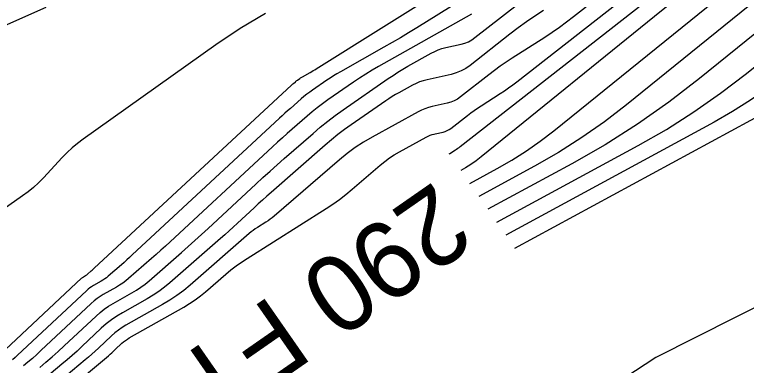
# Model space of a CAD drawing. Extents: x 1768942 to 1774819, y 723037 to 732099.
# Drawn here: x 1770698.5 to 1770755.9, y 726606.2 to 726633.7 of the extents above; entities that cross this region are included whole.
import ezdxf

# ---------------------------------------------------------------- set-up
doc = ezdxf.new("R2010")
doc.units = 0
doc.layers.add('R_Contour Annot', color=7, linetype='Continuous')
doc.layers.add('R_Contours', color=7, linetype='Continuous')

msp = doc.modelspace()

# ---------------------------------------------------------------- linework, layer by layer
at = {"layer": 'R_Contours'}
for points in [[(1770734.178, 726620.492), (1770736.32, 726621.654), (1770737.482, 726622.319), (1770738.61, 726623.036), (1770739.704, 726623.803), (1770740.764, 726624.622), (1770770.803, 726648.931), (1770771.01, 726649.103), (1770771.211, 726649.281), (1770771.408, 726649.465), (1770771.599, 726649.654), (1770772.459, 726650.529), (1770772.596, 726650.666), (1770772.736, 726650.8), (1770772.879, 726650.931), (1770773.024, 726651.059), (1770773.61, 726651.567), (1770773.758, 726651.692), (1770773.909, 726651.812), (1770774.064, 726651.928), (1770774.222, 726652.04), (1770795.506, 726666.687)], [(1770796.101, 726665.831), (1770779.224, 726654.217), (1770778.742, 726653.876), (1770778.271, 726653.522), (1770777.81, 726653.155), (1770777.359, 726652.775), (1770775.575, 726651.229), (1770775.133, 726650.838), (1770774.699, 726650.439), (1770774.273, 726650.031), (1770773.855, 726649.615), (1770771.236, 726646.95), (1770770.653, 726646.374), (1770770.056, 726645.815), (1770769.442, 726645.274), (1770768.813, 726644.75), (1770746.468, 726626.666), (1770744.745, 726625.336), (1770742.966, 726624.088), (1770741.132, 726622.924), (1770739.243, 726621.842), (1770734.884, 726619.477)], [(1770798.2, 726666.01), (1770784.225, 726656.393), (1770783.421, 726655.823), (1770782.633, 726655.232), (1770781.862, 726654.618), (1770781.108, 726653.983), (1770778.126, 726651.399), (1770777.387, 726650.746), (1770776.662, 726650.078), (1770775.95, 726649.396), (1770775.252, 726648.7), (1770770.873, 726644.246), (1770769.899, 726643.283), (1770768.9, 726642.349), (1770767.874, 726641.444), (1770766.822, 726640.568), (1770752.171, 726628.711), (1770749.785, 726626.869), (1770747.322, 726625.141), (1770744.783, 726623.528), (1770742.167, 726622.031), (1770735.59, 726618.462)], [(1770736.296, 726617.447), (1770747.368, 726623.455), (1770749.588, 726624.726), (1770751.744, 726626.095), (1770753.835, 726627.562), (1770755.86, 726629.126), (1770764.832, 726636.386), (1770766.306, 726637.615), (1770767.744, 726638.883), (1770769.145, 726640.192), (1770770.51, 726641.541), (1770776.648, 726647.786), (1770777.627, 726648.762), (1770778.625, 726649.718), (1770779.641, 726650.654), (1770780.677, 726651.569), (1770784.858, 726655.191), (1770785.915, 726656.081), (1770786.995, 726656.941), (1770788.099, 726657.771), (1770789.227, 726658.57), (1770797.444, 726664.225)], [(1770797.312, 726662.869), (1770793.302, 726660.109), (1770792.31, 726659.406), (1770791.338, 726658.676), (1770790.387, 726657.919), (1770789.457, 726657.136), (1770783.228, 726651.739), (1770781.896, 726650.561), (1770780.587, 726649.357), (1770779.304, 726648.127), (1770778.044, 726646.871), (1770769.029, 726637.701), (1770767.84, 726636.525), (1770766.619, 726635.384), (1770765.365, 726634.278), (1770764.08, 726633.207), (1770758.875, 726628.995), (1770757.553, 726627.974), (1770756.188, 726627.016), (1770754.78, 726626.123), (1770753.33, 726625.292), (1770737.003, 726616.433)], [(1770737.709, 726615.418), (1770759.293, 726627.13), (1770759.972, 726627.519), (1770760.632, 726627.938), (1770761.271, 726628.386), (1770761.891, 726628.865), (1770764.329, 726630.838), (1770764.931, 726631.339), (1770765.518, 726631.857), (1770766.09, 726632.392), (1770766.647, 726632.943), (1770779.44, 726645.957), (1770780.98, 726647.493), (1770782.55, 726648.997), (1770784.15, 726650.469), (1770785.779, 726651.909), (1770794.896, 726659.807), (1770795.275, 726660.127), (1770795.662, 726660.435), (1770796.058, 726660.732), (1770796.462, 726661.019), (1770798.095, 726662.143)], [(1770732.564, 726622.812), (1770732.623, 726622.85), (1770733.047, 726623.121), (1770733.144, 726623.185), (1770733.239, 726623.25), (1770733.332, 726623.318), (1770733.424, 726623.388), (1770765.828, 726648.746)], [(1770731.47, 726624.384), (1770732.083, 726624.521), (1770732.249, 726624.567), (1770732.407, 726624.632), (1770732.556, 726624.713), (1770732.698, 726624.812), (1770733.985, 726625.823), (1770734.248, 726626.024), (1770734.515, 726626.218), (1770734.787, 726626.406), (1770735.064, 726626.587), (1770736.548, 726627.535), (1770736.886, 726627.757), (1770737.218, 726627.986), (1770737.544, 726628.223), (1770737.865, 726628.468), (1770761.892, 726647.27)], [(1770757.956, 726645.794), (1770742.307, 726633.548), (1770741.757, 726633.128), (1770741.197, 726632.722), (1770740.628, 726632.329), (1770740.049, 726631.95), (1770737.505, 726630.325), (1770737.031, 726630.014), (1770736.565, 726629.692), (1770736.107, 726629.358), (1770735.656, 726629.014), (1770733.45, 726627.282), (1770733.207, 726627.112), (1770732.951, 726626.973), (1770732.681, 726626.863), (1770732.396, 726626.783), (1770731.229, 726626.522), (1770730.941, 726626.448), (1770730.661, 726626.353), (1770730.387, 726626.239), (1770730.122, 726626.105), (1770726.517, 726624.125), (1770725.841, 726623.731), (1770725.188, 726623.302), (1770724.558, 726622.84), (1770723.952, 726622.344), (1770718.831, 726617.927), (1770718.678, 726617.8), (1770718.521, 726617.679), (1770718.36, 726617.564), (1770718.194, 726617.456), (1770717.522, 726617.033), (1770717.357, 726616.924), (1770717.196, 726616.809), (1770717.039, 726616.687), (1770716.887, 726616.56), (1770712.26, 726612.522), (1770711.748, 726612.098), (1770711.217, 726611.701), (1770710.665, 726611.331), (1770710.095, 726610.989), (1770707.223, 726609.366), (1770706.923, 726609.185), (1770706.637, 726608.987), (1770706.362, 726608.773), (1770706.1, 726608.541), (1770705.076, 726607.582), (1770704.818, 726607.343), (1770704.558, 726607.109), (1770704.294, 726606.878), (1770704.026, 726606.651), (1770699.549, 726602.898)], [(1770800.409, 726644.578), (1770793.481, 726644.385), (1770792.954, 726644.312), (1770792.494, 726644.122), (1770792.102, 726643.816), (1770791.778, 726643.394), (1770790.616, 726641.474), (1770790.305, 726641.012), (1770789.954, 726640.588), (1770789.563, 726640.2), (1770789.132, 726639.848), (1770774.363, 726628.963), (1770773.416, 726628.137), (1770772.65, 726627.19), (1770772.065, 726626.121), (1770771.662, 726624.931), (1770770.41, 726619.929), (1770769.992, 726618.762), (1770769.365, 726617.763), (1770768.528, 726616.931), (1770767.481, 726616.267), (1770748.765, 726606.836), (1770746.319, 726605.259)], [(1770757.447, 726640.582), (1770755.379, 726638.957), (1770753.317, 726637.324), (1770751.263, 726635.682), (1770749.215, 726634.031), (1770735.061, 726622.577), (1770734.664, 726622.27), (1770734.254, 726621.983), (1770733.831, 726621.714), (1770733.471, 726621.508)], [(1770696.898, 726606.649), (1770703.747, 726613.067), (1770703.782, 726613.098), (1770703.819, 726613.127), (1770703.858, 726613.154), (1770703.898, 726613.178), (1770704.063, 726613.272), (1770704.103, 726613.296), (1770704.143, 726613.322), (1770704.18, 726613.35), (1770704.217, 726613.38), (1770704.503, 726613.631), (1770704.563, 726613.683), (1770704.622, 726613.736), (1770704.68, 726613.789), (1770704.739, 726613.842), (1770720.194, 726628.196), (1770720.232, 726628.231), (1770720.27, 726628.266), (1770720.308, 726628.3), (1770720.347, 726628.334), (1770720.501, 726628.469), (1770720.54, 726628.503), (1770720.58, 726628.535), (1770720.621, 726628.566), (1770720.663, 726628.596), (1770720.862, 726628.734), (1770720.91, 726628.766), (1770720.959, 726628.797), (1770721.008, 726628.827), (1770721.058, 726628.856), (1770721.671, 726629.202), (1770721.79, 726629.27), (1770721.908, 726629.339), (1770722.025, 726629.409), (1770722.141, 726629.481), (1770738.054, 726639.453)], [(1770735.188, 726635.945), (1770730.023, 726632.708), (1770729.382, 726632.311), (1770728.735, 726631.922), (1770728.084, 726631.54), (1770727.429, 726631.166), (1770724.038, 726629.256), (1770723.763, 726629.097), (1770723.491, 726628.931), (1770723.223, 726628.759), (1770722.96, 726628.581), (1770721.855, 726627.816), (1770721.625, 726627.651), (1770721.399, 726627.48), (1770721.178, 726627.302), (1770720.963, 726627.119), (1770720.11, 726626.371), (1770719.897, 726626.183), (1770719.686, 726625.994), (1770719.476, 726625.803), (1770719.268, 726625.611), (1770707.714, 726614.88), (1770707.503, 726614.686), (1770707.291, 726614.494), (1770707.078, 726614.303), (1770706.862, 726614.114), (1770705.825, 726613.209), (1770705.694, 726613.1), (1770705.557, 726612.998), (1770705.416, 726612.903), (1770705.269, 726612.815), (1770704.673, 726612.478), (1770704.527, 726612.39), (1770704.387, 726612.293), (1770704.253, 726612.189), (1770704.125, 726612.076), (1770698.729, 726607.018), (1770698.532, 726606.836), (1770698.332, 726606.657)], [(1770700.464, 726606.049), (1770700.954, 726606.466), (1770701.439, 726606.89), (1770701.917, 726607.32), (1770702.39, 726607.757), (1770704.882, 726610.092), (1770705.195, 726610.369), (1770705.523, 726610.625), (1770705.866, 726610.861), (1770706.223, 726611.078), (1770707.682, 726611.902), (1770708.041, 726612.117), (1770708.387, 726612.349), (1770708.721, 726612.599), (1770709.043, 726612.866), (1770711.581, 726615.08), (1770712.107, 726615.543), (1770712.63, 726616.01), (1770713.149, 726616.481), (1770713.665, 726616.956), (1770717.414, 726620.439), (1770717.964, 726620.946), (1770718.518, 726621.449), (1770719.075, 726621.949), (1770719.636, 726622.444), (1770721.886, 726624.417), (1770722.455, 726624.902), (1770723.037, 726625.37), (1770723.632, 726625.822), (1770724.241, 726626.256), (1770727.79, 726628.716), (1770728.166, 726628.969), (1770728.546, 726629.214), (1770728.933, 726629.45), (1770729.325, 726629.676), (1770731.158, 726630.709), (1770731.43, 726630.849), (1770731.71, 726630.969), (1770731.997, 726631.067), (1770732.293, 726631.144), (1770733.492, 726631.412), (1770733.785, 726631.494), (1770734.063, 726631.607), (1770734.326, 726631.751), (1770734.575, 726631.925), (1770738.999, 726635.397)], [(1770691.935, 726630.328), (1770700.961, 726634.315)], [(1770739.946, 726634.062), (1770739.274, 726633.622), (1770738.614, 726633.165), (1770737.965, 726632.693), (1770737.328, 726632.205), (1770734.202, 726629.752), (1770733.859, 726629.512), (1770733.495, 726629.314), (1770733.112, 726629.158), (1770732.709, 726629.045), (1770730.826, 726628.625), (1770730.532, 726628.548), (1770730.245, 726628.451), (1770729.966, 726628.335), (1770729.694, 726628.198), (1770728.624, 726627.61), (1770728.358, 726627.46), (1770728.097, 726627.303), (1770727.84, 726627.139), (1770727.587, 726626.968), (1770724.888, 726625.099), (1770724.36, 726624.722), (1770723.844, 726624.33), (1770723.339, 726623.924), (1770722.846, 726623.504), (1770718.596, 726619.776), (1770718.261, 726619.481), (1770717.929, 726619.183), (1770717.599, 726618.883), (1770717.271, 726618.58), (1770715.963, 726617.365), (1770715.635, 726617.063), (1770715.304, 726616.763), (1770714.971, 726616.466), (1770714.636, 726616.171), (1770710.652, 726612.694), (1770710.235, 726612.348), (1770709.802, 726612.025), (1770709.353, 726611.724), (1770708.888, 726611.446), (1770706.961, 726610.357), (1770706.516, 726610.087), (1770706.089, 726609.793), (1770705.681, 726609.474), (1770705.291, 726609.13), (1770703.769, 726607.703), (1770703.386, 726607.349), (1770702.998, 726607), (1770702.605, 726606.657), (1770702.208, 726606.319), (1770699.183, 726603.783)], [(1770718.169, 726633.81), (1770716.187, 726632.651), (1770714.271, 726631.371), (1770703.862, 726623.955), (1770703.428, 726623.629), (1770703.012, 726623.282), (1770702.614, 726622.915), (1770702.235, 726622.527), (1770700.753, 726620.932), (1770700.373, 726620.545), (1770699.974, 726620.179), (1770699.557, 726619.834), (1770699.121, 726619.511), (1770694.916, 726616.564)], [(1770734.32, 726633.768), (1770727.019, 726629.656), (1770726.518, 726629.366), (1770726.023, 726629.065), (1770725.537, 726628.752), (1770725.057, 726628.428), (1770723.048, 726627.036), (1770722.628, 726626.736), (1770722.218, 726626.425), (1770721.816, 726626.102), (1770721.424, 726625.768), (1770719.873, 726624.407), (1770719.486, 726624.066), (1770719.102, 726623.721), (1770718.72, 726623.374), (1770718.341, 726623.025), (1770710.689, 726615.918), (1770710.326, 726615.584), (1770709.961, 726615.252), (1770709.592, 726614.923), (1770709.222, 726614.597), (1770707.434, 726613.037), (1770707.208, 726612.849), (1770706.972, 726612.674), (1770706.728, 726612.51), (1770706.476, 726612.359), (1770705.448, 726611.778), (1770705.196, 726611.626), (1770704.955, 726611.459), (1770704.724, 726611.279), (1770704.504, 726611.084), (1770700.56, 726607.388), (1770700.225, 726607.078), (1770699.886, 726606.773), (1770699.542, 726606.473), (1770699.195, 726606.178)], [(1770703.024, 726604.618), (1770705.845, 726606.983), (1770705.982, 726607.1), (1770706.117, 726607.218), (1770706.251, 726607.338), (1770706.383, 726607.46), (1770706.909, 726607.953), (1770707.043, 726608.071), (1770707.184, 726608.182), (1770707.331, 726608.283), (1770707.484, 726608.376), (1770711.768, 726610.797), (1770712.215, 726611.065), (1770712.647, 726611.354), (1770713.064, 726611.665), (1770713.465, 726611.998), (1770715.04, 726613.373), (1770715.44, 726613.708), (1770715.852, 726614.028), (1770716.276, 726614.33), (1770716.713, 726614.617), (1770722.915, 726618.523), (1770723.447, 726618.872), (1770723.964, 726619.24), (1770724.467, 726619.628), (1770724.957, 726620.034), (1770727.156, 726621.931), (1770727.51, 726622.22), (1770727.877, 726622.49), (1770728.258, 726622.74), (1770728.653, 726622.97), (1770730.756, 726624.125), (1770730.911, 726624.203), (1770731.07, 726624.27), (1770731.234, 726624.325), (1770731.402, 726624.369), (1770731.41, 726624.371)]]:
    msp.add_lwpolyline(points, dxfattribs=at)

# ---------------------------------------------------------------- texts
at = {"layer": 'R_Contour Annot'}
msp.add_text('290 FT', height=6, rotation=214.83188, dxfattribs=at).set_placement((1770731.444, 726620.74))

doc.saveas('drawing.dxf')
